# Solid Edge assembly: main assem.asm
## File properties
Author: Vicky Raina
Template: Normal.asm
Last saved by: MYPC
Revision: 12
Application: Solid Edge
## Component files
master rod.par
piston.par
piston pin.par
arti subassm.asm
piston pin plug.par
piston ring.par
master rod bearing.par
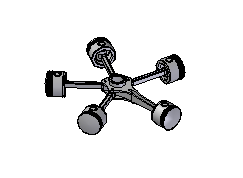
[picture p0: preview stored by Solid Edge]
